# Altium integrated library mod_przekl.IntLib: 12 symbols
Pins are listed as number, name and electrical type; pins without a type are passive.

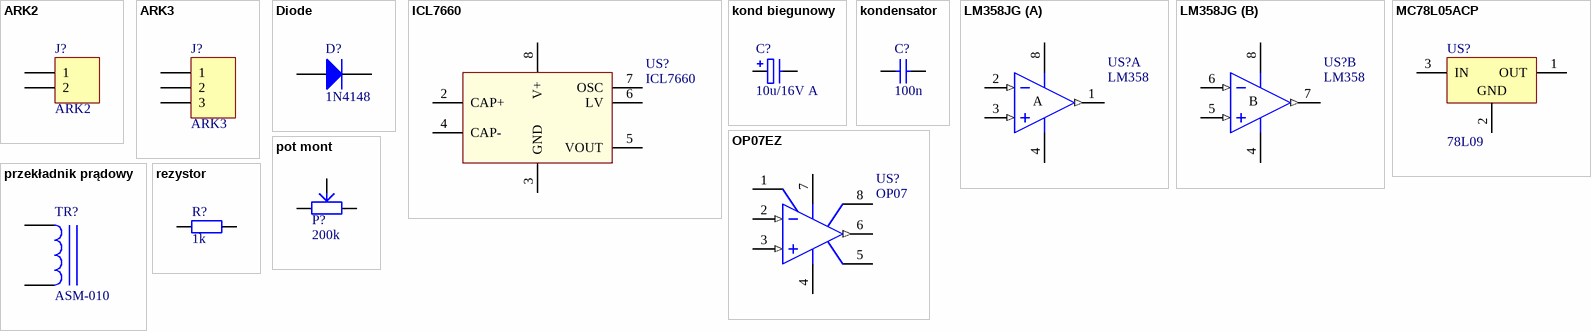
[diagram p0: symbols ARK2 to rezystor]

## ARK2
designator J?
footprint ARK2 3,5mm
footprint ARK2 5mm
footprint ARK2 7,5mm
pins: 1, 2

## ARK3
designator J?
footprint ARK3 3,5mm
footprint ARK3 5mm
footprint ARK3 7,5mm
pins: 1, 2, 3

## Diode
designator D?, comment 1N4148
Default Diode
footprint dioda 10mm
footprint dioda 17,5mm
footprint dioda 7,5mm
footprint dioda MINIMELF (SMT LED; 2 Flat Leads)
pins: 1 A, 2 K

## ICL7660
designator US?
footprint DIP8
footprint SO8-150mil
pins: 2 CAP+, 3 GND, 4 CAP-, 5 VOUT, 6 LV, 7 OSC, 8 V+

## kond biegunowy
designator C?, comment 10u/16V A
Polarized Capacitor
footprint Tantal B 3528-1411 (Capacitor, SM Tantalum; Body 3.5 x 2.8 mm (LxW typ))
footprint Tantal C 6032-2412 (Capacitor, SM Tantalum; Body 6.0 x 3.2 mm (LxW typ))
footprint Tantal D 7343-2917 (Capacitor, SM Tantalum; Body 7.3 x 4.3 mm (LxW typ))
footprint 2,5/5mm elektrolit
footprint 3,5/7mm elektrolit
footprint 5/10mm elektrolit
footprint 2,5/7mm elektrolit
footprint 7,5/16mm elektrolit
footprint 5/12,5mm elektrolit
footprint Tantal A 3216-1206 (Capacitor, SM Tantalum; Body 3.2 x 1.6 mm (LxW typ))
footprint A SMD elektrolit
footprint B SMD elektrolit
footprint C SMD elektrolit
footprint D SMD elektrolit
footprint E SMD elektrolit
footprint F SMD elektrolit
pins: 1, 2
1 alternate drawing of the same symbol

## kondensator
designator C?, comment 100n
footprint kond 2,5mm
footprint kond 7,5mm
footprint kond 10mm
footprint MELF-0805 (Metal Electrode Face (MELF) Resistor; Body 2 x 1.4 mm (LxDia))
footprint MELF-1206 (Metal Electrode Face (MELF) Resistor; Body 3.2 x 1.8 mm (LxDia))
footprint kond 15mm
footprint kond 5mm chudy
footprint kond 5mm gruby
footprint kond 5mm sredni
pins: 1, 2

## LM358JG
designator US?, comment LM358
Dual Operational Amplifier
footprint JG008 (DIP; 8 Leads; Row Spacing 7.62 mm; Pitch 2.54 mm)
3D model JG008 (DIP; 8 Leads; Row Spacing 7.62 mm; Pitch 2.54 mm)
simulation model LM358 (SUBCKT)
pins on every part: 4 V- (power), 8 V+ (power)
part A pins: 1 OUT (out), 2 IN- (in), 3 IN+ (in)
part B pins: 5 IN+ (in), 6 IN- (in), 7 OUT (out)

## MC78L05ACP
designator US?, comment 78L09
3-Terminal Low-Current Positive Fixed Voltage Regulator
footprint 29-04 (TO, Flat Index; 3 In-Line, Axial Leads; Body Dia. 4.8mm; Leads 0.48 x 0.5 mm (max))
pins: 1 OUT (power), 2 GND (power), 3 IN (power)

## OP07EZ
designator US?, comment OP07
Ultra-Low Offset Voltage Operational Amplifier; Note: Pin 5 is not connected.
footprint Q-8 (DIP; 8 Leads; Row Spacing 7.62 mm; Pitch 2.54 mm)
3D model Q-8 (DIP; 8 Leads; Row Spacing 7.62 mm; Pitch 2.54 mm)
simulation model OP07E (SUBCKT)
pins: 1 VOSTRIM, 2 IN- (in), 3 IN+ (in), 4 V- (power), 5 NC, 6 OUT (out), 7 V+ (power), 8 VOSTRIM

## pot mont
designator P?, comment 200k
footprint helitrim 5x10mm
footprint pot mont poziom
pins: a, b, c

## przekładnik prądowy
designator TR?, comment ASM-010
footprint TALEMA AS10x
pins: 1, 2

## rezystor
designator R?, comment 1k
footprint rez 7,5mm
footprint rez 10mm
footprint rez 12,5mm
footprint rez 15mm
footprint rez 17,5mm
footprint MELF-0805 (Metal Electrode Face (MELF) Resistor; Body 2 x 1.4 mm (LxDia))
footprint MELF-1206 (Metal Electrode Face (MELF) Resistor; Body 3.2 x 1.8 mm (LxDia))
footprint rez_bocznik 20mm
pins: 1, 2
